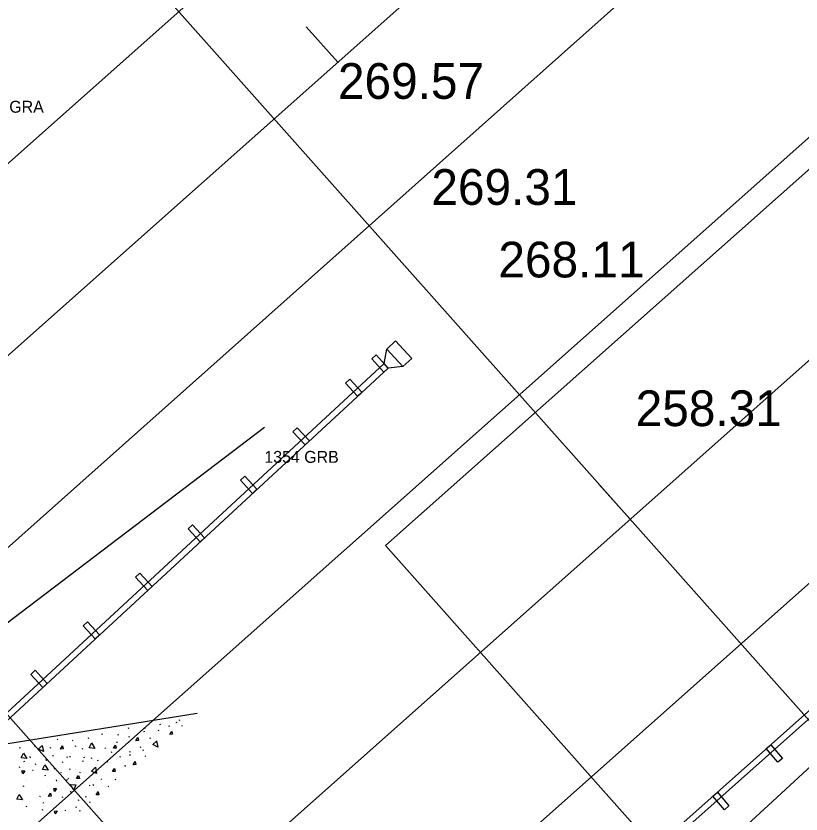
# Model space of a CAD drawing. Extents: x 49683 to 58852, y 49525 to 54803.
# Drawn here: x 53938 to 54003.9, y 51882.6 to 51949.6 of the extents above; entities that cross this region are included whole.
import ezdxf

# ---------------------------------------------------------------- set-up
doc = ezdxf.new("R2010")
doc.units = 0
for name, color, linetype in [('Level 1', 7, 'Continuous'), ('Level 11', 7, 'Continuous'), ('Level 13', 7, 'Continuous'), ('Level 19', 7, 'Continuous'), ('Level 20', 7, 'Continuous'), ('Level 27', 7, 'Continuous'), ('Level 29', 7, 'Continuous'), ('Level 3', 7, 'Continuous'), ('Level 32', 7, 'Continuous'), ('Level 50', 7, 'Continuous'), ('Level 57', 7, 'Continuous'), ('Level 63', 7, 'Continuous'), ('Level 7', 7, 'Continuous'), ('Level 8', 7, 'Continuous')]:
    doc.layers.add(name, color=color, linetype=linetype)

msp = doc.modelspace()

# ---------------------------------------------------------------- linework, layer by layer
at = {"layer": 'Level 1'}
for p, q in [((52544.807, 50683.302), (55534.583, 53340.862)), ((53965.019, 51945.704), (53962.362, 51948.693))]:
    msp.add_line(p, q, dxfattribs=at)
at = {"layer": 'Level 11'}
msp.add_line((53944.235, 51830.768), (54450.301, 52297.6), dxfattribs=at)
at = {"layer": 'Level 13'}
for p in [(55279.532, 53069.998), (53996.93, 51873.722)]:
    msp.add_line(p, (53969.027, 51905.114), dxfattribs=at)
at = {"layer": 'Level 19'}
for p, q in [((52714.154, 50773.623), (54181.768, 52078.16)), ((53989.569, 51907.317), (53986.911, 51910.307))]:
    msp.add_line(p, q, dxfattribs=at)
at = {"layer": 'Level 20'}
for p, q in [((53893.546, 51840.696), (54172.467, 52088.624)), ((53913.315, 51820.805), (54191.069, 52067.696))]:
    msp.add_line(p, q, dxfattribs=at)
at = {"layer": 'Level 27'}
for p, q in [((53961.769, 51853.172), (54196.384, 52061.717)), ((53962.101, 51852.798), (54196.716, 52061.343)), ((53969.128, 51921.62), (53969.862, 51922.299)), ((53971.221, 51920.831), (53969.862, 51922.299)), ((53968.904, 51920.39), (53969.128, 51921.62)), ((53970.487, 51920.152), (53969.128, 51921.62)), ((53970.487, 51920.152), (53971.221, 51920.831)), ((53932.197, 51886.425), (53968.904, 51920.39)), ((53932.537, 51886.058), (53969.243, 51920.023)), ((53969.243, 51920.023), (53968.904, 51920.39)), ((53970.487, 51920.152), (53969.243, 51920.023))]:
    msp.add_line(p, q, dxfattribs=at)
for points in [[(53969.243, 51920.023), (53968.872, 51919.688), (53967.867, 51920.801), (53968.237, 51921.136)], [(53967.041, 51917.985), (53966.674, 51917.645), (53965.654, 51918.746), (53966.021, 51919.086)], [(53962.636, 51913.91), (53962.269, 51913.57), (53961.25, 51914.67), (53961.616, 51915.01)], [(53958.231, 51909.834), (53957.864, 51909.494), (53956.845, 51910.594), (53957.212, 51910.934)], [(53953.826, 51905.758), (53953.46, 51905.418), (53952.44, 51906.518), (53952.807, 51906.858)], [(53949.422, 51901.682), (53949.055, 51901.342), (53948.035, 51902.442), (53948.402, 51902.782)], [(53945.017, 51897.606), (53944.65, 51897.266), (53943.631, 51898.366), (53943.997, 51898.706)], [(53940.612, 51893.53), (53940.246, 51893.19), (53939.226, 51894.29), (53939.593, 51894.63)], [(54002.348, 51887.226), (54001.965, 51886.905), (54001.003, 51888.056), (54001.387, 51888.377)], [(53997.864, 51883.24), (53997.48, 51882.919), (53996.519, 51884.07), (53996.902, 51884.391)]]:
    msp.add_lwpolyline(points, close=True, dxfattribs=at)
at = {"layer": 'Level 29'}
for p, q in [((52714.154, 50773.623), (54181.768, 52078.16)), ((53989.569, 51907.317), (53986.911, 51910.307))]:
    msp.add_line(p, q, dxfattribs=at)
at = {"layer": 'Level 3'}
for p, q in [((53883.273, 51889.178), (54069.537, 52054.718)), ((53898.742, 51870.567), (54083.389, 52035.124))]:
    msp.add_line(p, q, dxfattribs=at)
at = {"layer": 'Level 50'}
for p, q in [((53909.845, 51997.007), (54069.292, 51817.628)), ((53872.475, 51963.789), (54031.921, 51784.41))]:
    msp.add_line(p, q, dxfattribs=at)
at = {"layer": 'Level 63'}
for p, q in [((54172.467, 52088.624), (53929.444, 51872.604)), ((53938.745, 51862.141), (54181.768, 52078.16)), ((53938.745, 51862.141), (54181.768, 52078.16)), ((54191.069, 52067.696), (53948.046, 51851.677))]:
    msp.add_line(p, q, dxfattribs=at)
at = {"layer": 'Level 7'}
msp.add_line((53922.854, 51887.665), (53958.852, 51915.059), dxfattribs=at)
at = {"layer": 'Level 8'}
for p, q in [((53935.625, 51888.219), (53953.195, 51891.04)), ((53951.433, 51890.314), (53951.458, 51890.226)), ((53951.692, 51890.508), (53951.717, 51890.42)), ((53947.407, 51889.839), (53947.431, 51889.752)), ((53948.779, 51889.828), (53948.803, 51889.74)), ((53949.944, 51889.633), (53949.968, 51889.545)), ((53950.065, 51890.146), (53950.09, 51890.058)), ((53950.818, 51889.99), (53950.842, 51889.902)), ((53951.98, 51889.935), (53951.916, 51889.955)), ((53944.059, 51888.987), (53944.083, 51888.9)), ((53945.205, 51889.332), (53945.23, 51889.244)), ((53946.545, 51889.277), (53946.569, 51889.189)), ((53947.471, 51889.1), (53947.496, 51889.012)), ((53948.738, 51889.545), (53948.763, 51889.458)), ((53949.232, 51888.985), (53949.256, 51888.897)), ((53939.549, 51888.32), (53939.573, 51888.232)), ((53941.504, 51888.801), (53941.444, 51888.86)), ((53942.79, 51888.71), (53942.726, 51888.729)), ((53942.951, 51888.305), (53942.976, 51888.217)), ((53945.937, 51888.773), (53945.937, 51888.773)), ((53946.066, 51888.879), (53946.066, 51888.879)), ((53946.503, 51888.557), (53946.439, 51888.576)), ((53947.419, 51888.629), (53947.443, 51888.541)), ((53938.29, 51888.175), (53938.314, 51888.087)), ((53940.867, 51888.166), (53940.892, 51888.078)), ((53943.554, 51888.096), (53943.578, 51888.008)), ((53945.519, 51888.053), (53945.456, 51888.072)), ((53945.994, 51887.819), (53946.019, 51887.731)), ((53947.516, 51887.851), (53947.54, 51887.763)), ((53948.422, 51888.24), (53948.447, 51888.152)), ((53948.649, 51887.981), (53948.673, 51887.893)), ((53938.643, 51887.037), (53938.667, 51886.949)), ((53939.216, 51887.291), (53939.189, 51887.378)), ((53940.317, 51887.485), (53940.341, 51887.397)), ((53940.557, 51887.039), (53940.53, 51887.126)), ((53941.074, 51887.495), (53941.098, 51887.407)), ((53941.883, 51886.976), (53941.907, 51886.888)), ((53942.271, 51887.397), (53942.296, 51887.309)), ((53942.501, 51887.431), (53942.525, 51887.343)), ((53943.586, 51887.059), (53943.611, 51886.971)), ((53943.696, 51887.365), (53943.72, 51887.277)), ((53944.317, 51887.299), (53944.341, 51887.211)), ((53944.829, 51887.106), (53944.853, 51887.018)), ((53945.649, 51887.005), (53945.673, 51886.917)), ((53946.707, 51887.43), (53946.731, 51887.342)), ((53947.604, 51887.486), (53947.544, 51887.545)), ((53948.89, 51887.395), (53948.826, 51887.414)), ((53938.254, 51886.551), (53938.278, 51886.463)), ((53939.614, 51886.81), (53939.638, 51886.723)), ((53941.2, 51886.422), (53941.224, 51886.334)), ((53942.498, 51886.393), (53942.522, 51886.305)), ((53942.977, 51886.338), (53942.977, 51886.338)), ((53947.127, 51886.652), (53947.152, 51886.564)), ((53939.379, 51886.247), (53939.443, 51886.23)), ((53940.456, 51885.749), (53940.429, 51885.836)), ((53941.716, 51886.066), (53941.781, 51886.048)), ((53943.413, 51886.016), (53943.349, 51886.035)), ((53938.596, 51884.945), (53938.62, 51884.858)), ((53938.859, 51885.404), (53938.859, 51885.404)), ((53941.362, 51885.417), (53941.386, 51885.329)), ((53942.268, 51885.482), (53942.293, 51885.394)), ((53942.43, 51885.512), (53942.366, 51885.531)), ((53944.139, 51884.98), (53944.204, 51884.962)), ((53944.515, 51884.945), (53944.455, 51885.004)), ((53945.106, 51885.514), (53945.17, 51885.497)), ((53946.378, 51885.404), (53946.351, 51885.491)), ((53940.603, 51884.837), (53940.603, 51884.837)), ((53941.228, 51884.758), (53941.252, 51884.67)), ((53942.56, 51884.464), (53942.584, 51884.376)), ((53944.586, 51884.671), (53944.586, 51884.671)), ((53944.711, 51884.781), (53944.711, 51884.781)), ((53944.878, 51884.372), (53944.851, 51884.459)), ((53945.801, 51884.854), (53945.737, 51884.873)), ((53940.056, 51884.011), (53939.992, 51884.03)), ((53941.936, 51883.921), (53941.909, 51884.008)), ((53943.276, 51883.669), (53943.249, 51883.756)), ((53943.822, 51884.056), (53943.847, 51883.968)), ((53944.178, 51883.602), (53944.203, 51883.514)), ((53938.854, 51883.257), (53938.878, 51883.169)), ((53940.186, 51882.963), (53940.21, 51882.875)), ((53940.324, 51883.475), (53940.26, 51883.494)), ((53943.013, 51883.181), (53943.037, 51883.093)), ((53942.098, 51882.877), (53942.163, 51882.86)), ((53943.37, 51882.767), (53943.343, 51882.854))]:
    msp.add_line(p, q, dxfattribs=at)
for points in [[(53948.222, 51888.974), (53948.283, 51888.725), (53948.052, 51888.714), (53948.222, 51888.974)], [(53951.077, 51889.504), (53951.138, 51889.255), (53950.907, 51889.245), (53951.077, 51889.504)], [(53940.189, 51888.324), (53940.296, 51887.801), (53939.87, 51888.013), (53940.182, 51888.318)], [(53941.887, 51888.279), (53941.948, 51888.03), (53941.717, 51888.019), (53941.887, 51888.279)], [(53944.334, 51888.526), (53944.613, 51888.071), (53944.14, 51888.125), (53944.329, 51888.518)], [(53946.345, 51888.343), (53946.406, 51888.094), (53946.175, 51888.084), (53946.345, 51888.343)], [(53949.792, 51888.698), (53949.899, 51888.175), (53949.473, 51888.387), (53949.785, 51888.692)], [(53938.619, 51887.679), (53938.898, 51887.224), (53938.425, 51887.278), (53938.614, 51887.671)], [(53947.987, 51886.963), (53948.049, 51886.714), (53947.818, 51886.704), (53947.987, 51886.963)], [(53940.421, 51886.696), (53940.7, 51886.242), (53940.227, 51886.295), (53940.417, 51886.688)], [(53944.655, 51886.483), (53944.762, 51885.96), (53944.336, 51886.172), (53944.648, 51886.477)], [(53946.253, 51886.393), (53946.314, 51886.144), (53946.083, 51886.133), (53946.253, 51886.393)], [(53938.563, 51885.931), (53938.494, 51886.178), (53938.725, 51886.196), (53938.563, 51885.931)], [(53943.255, 51885.802), (53943.316, 51885.553), (53943.085, 51885.543), (53943.255, 51885.802)], [(53942.845, 51884.591), (53942.552, 51885.037), (53943.026, 51884.998), (53942.849, 51884.599)], [(53940.881, 51884.301), (53940.942, 51884.052), (53940.711, 51884.042), (53940.881, 51884.301)], [(53941.234, 51884.444), (53941.165, 51884.691), (53941.395, 51884.708), (53941.234, 51884.444)], [(53944.898, 51884.423), (53944.959, 51884.174), (53944.728, 51884.163), (53944.898, 51884.423)], [(53938.252, 51884.201), (53938.531, 51883.746), (53938.058, 51883.8), (53938.247, 51884.193)], [(53941.283, 51882.561), (53941.214, 51882.808), (53941.444, 51882.826), (53941.283, 51882.561)]]:
    msp.add_lwpolyline(points, dxfattribs=at)

# ---------------------------------------------------------------- texts
at = {"layer": 'Level 32'}
for s, p in [('269.57', (53965.029, 51942.633)), ('269.31', (53972.875, 51933.73)), ('268.11', (53978.503, 51927.633)), ('258.31', (53990.033, 51915.141))]:
    msp.add_text(s, height=3, dxfattribs=at).set_placement(p)
at = {"layer": 'Level 57'}
for s, p in [('1355 GRA', (53934.083, 51941.47)), ('1354 GRB', (53958.852, 51912.059))]:
    msp.add_text(s, height=1, dxfattribs=at).set_placement(p)

doc.saveas('drawing.dxf')
